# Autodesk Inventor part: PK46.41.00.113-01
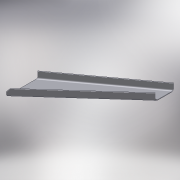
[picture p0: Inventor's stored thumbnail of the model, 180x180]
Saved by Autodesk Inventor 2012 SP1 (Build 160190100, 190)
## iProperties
Created: 2005-07
Part Number: PK46.41.00.113-01
Material: Steel, Mild
Document SubType Name: Modeling
Designer: PVitaliy
Manufacturer: Standard
Standards Organization: Custom
Density: 7.86 g/cm^3
Author: PVitaliy
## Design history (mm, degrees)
derived "PK46.41.00.113.ipt"
body "Solid1"
tag "TaggingFeature2"
feature "DerivedBody::PK46.41.00.113.ipt" dims "d3" = 10
